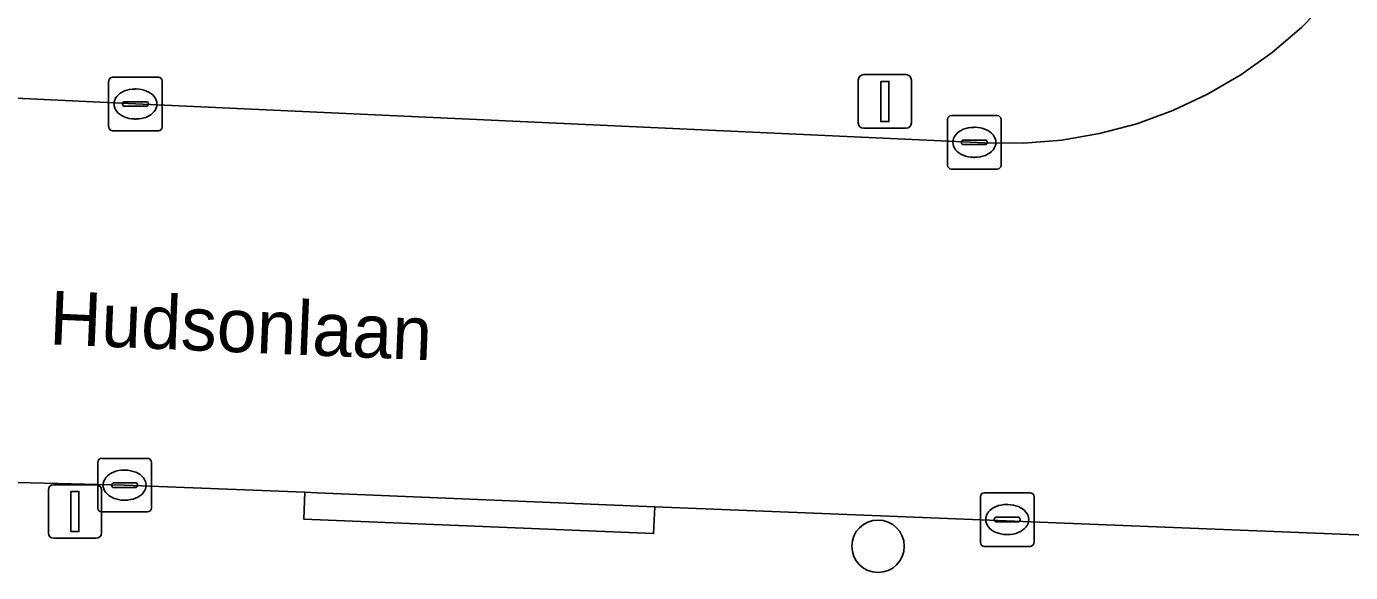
# Model space of a CAD drawing. Extents: x 161248 to 161848, y 384871 to 385383.
# Drawn here: x 161662.78 to 161687.48, y 384939.05 to 384949.24 of the extents above; entities that cross this region are included whole.
import ezdxf

# ---------------------------------------------------------------- set-up
doc = ezdxf.new("R2010")
doc.units = 0
for name, color, linetype in [('IMGEO_Boom', 7, 'Continuous'), ('IMGEO_Kolk', 7, 'Continuous'), ('IMGEO_Lichtmast', 7, 'Continuous'), ('IMGEO_Openbare_ruimte_label', 7, 'Continuous'), ('IMGEO_Rijbaan_lokaal_open', 7, 'Continuous'), ('IMGEO_Voetpad_open', 7, 'Continuous')]:
    doc.layers.add(name, color=color, linetype=linetype)

msp = doc.modelspace()

# ---------------------------------------------------------------- linework, layer by layer
at = {"layer": 'IMGEO_Boom'}
msp.add_circle((161678.665, 384939.544), 0.489, dxfattribs=at)
at = {"layer": 'IMGEO_Kolk'}
for p, q in [((161664.387, 384948.293), (161665.239, 384948.293)), ((161664.312, 384947.367), (161664.312, 384948.219)), ((161664.8, 384948.073), (161664.825, 384948.073)), ((161665.313, 384948.219), (161665.313, 384947.367)), ((161664.571, 384947.787), (161664.571, 384947.799)), ((161665.009, 384947.75), (161664.611, 384947.75)), ((161664.614, 384947.836), (161665.012, 384947.836)), ((161665.055, 384947.799), (161665.055, 384947.787)), ((161664.823, 384947.513), (161664.798, 384947.513)), ((161679.961, 384946.652), (161679.961, 384947.504)), ((161680.036, 384947.578), (161680.888, 384947.578)), ((161680.962, 384947.504), (161680.962, 384946.652)), ((161665.239, 384947.293), (161664.387, 384947.293)), ((161680.449, 384947.358), (161680.474, 384947.358)), ((161680.22, 384947.072), (161680.22, 384947.084)), ((161680.658, 384947.035), (161680.26, 384947.035)), ((161680.263, 384947.121), (161680.661, 384947.121)), ((161680.704, 384947.084), (161680.704, 384947.072)), ((161680.472, 384946.798), (161680.447, 384946.798)), ((161680.888, 384946.578), (161680.036, 384946.578)), ((161664.109, 384940.258), (161664.109, 384941.11)), ((161664.184, 384941.184), (161665.036, 384941.184)), ((161665.11, 384941.11), (161665.11, 384940.258)), ((161664.597, 384940.964), (161664.622, 384940.964)), ((161664.368, 384940.678), (161664.368, 384940.69)), ((161664.806, 384940.641), (161664.408, 384940.641)), ((161664.411, 384940.727), (161664.809, 384940.727)), ((161664.852, 384940.69), (161664.852, 384940.678)), ((161664.62, 384940.404), (161664.595, 384940.404)), ((161680.574, 384939.617), (161680.574, 384940.469)), ((161680.649, 384940.543), (161681.501, 384940.543)), ((161681.575, 384940.469), (161681.575, 384939.617)), ((161665.036, 384940.184), (161664.184, 384940.184)), ((161680.876, 384940.086), (161681.274, 384940.086)), ((161681.062, 384940.323), (161681.087, 384940.323)), ((161680.833, 384940.037), (161680.833, 384940.049)), ((161681.271, 384940), (161680.873, 384940)), ((161681.317, 384940.049), (161681.317, 384940.037)), ((161681.085, 384939.763), (161681.06, 384939.763)), ((161681.501, 384939.543), (161680.649, 384939.543))]:
    msp.add_line(p, q, dxfattribs=at)
for points in [[(161664.387, 384948.293), (161665.239, 384948.293)], [(161664.312, 384947.367), (161664.312, 384948.219)], [(161665.313, 384948.219), (161665.313, 384947.367)], [(161679.961, 384946.652), (161679.961, 384947.504)], [(161680.036, 384947.578), (161680.888, 384947.578)], [(161680.962, 384947.504), (161680.962, 384946.652)], [(161665.239, 384947.293), (161664.387, 384947.293)], [(161680.888, 384946.578), (161680.036, 384946.578)], [(161664.109, 384940.258), (161664.109, 384941.11)], [(161664.184, 384941.184), (161665.036, 384941.184)], [(161665.11, 384941.11), (161665.11, 384940.258)], [(161680.574, 384939.617), (161680.574, 384940.469)], [(161680.649, 384940.543), (161681.501, 384940.543)], [(161681.575, 384940.469), (161681.575, 384939.617)], [(161665.036, 384940.184), (161664.184, 384940.184)], [(161681.501, 384939.543), (161680.649, 384939.543)]]:
    msp.add_lwpolyline(points, dxfattribs=at)
for centre, radius, start, end in [((161664.389, 384948.217), 0.0765, 91.552, 178.448), ((161664.389, 384948.217), 0.0765, 91.552, 178.448), ((161665.237, 384948.217), 0.0765, 1.552, 88.448), ((161665.237, 384948.217), 0.0765, 1.552, 88.448), ((161664.611, 384947.796), 0.0403, 85.8775, 175.7526), ((161664.608, 384947.786), 0.0366, 178.938, 274.7102), ((161665.012, 384947.793), 0.043, 264.8664, 352.4533), ((161665.016, 384947.798), 0.0386, 1.7309, 96.639), ((161680.038, 384947.502), 0.0765, 91.552, 178.448), ((161680.038, 384947.502), 0.0765, 91.552, 178.448), ((161680.886, 384947.502), 0.0765, 1.552, 88.448), ((161680.886, 384947.502), 0.0765, 1.552, 88.448), ((161664.389, 384947.369), 0.0765, 181.552, 268.448), ((161664.389, 384947.369), 0.0765, 181.552, 268.448), ((161665.237, 384947.369), 0.0765, 271.552, 358.448), ((161665.237, 384947.369), 0.0765, 271.552, 358.448), ((161680.26, 384947.081), 0.0403, 85.8775, 175.7526), ((161680.257, 384947.071), 0.0366, 178.938, 274.7102), ((161680.661, 384947.078), 0.043, 264.8664, 352.4533), ((161680.665, 384947.083), 0.0386, 1.7309, 96.639), ((161680.038, 384946.654), 0.0765, 181.552, 268.448), ((161680.038, 384946.654), 0.0765, 181.552, 268.448), ((161680.886, 384946.654), 0.0765, 271.552, 358.448), ((161680.886, 384946.654), 0.0765, 271.552, 358.448), ((161664.186, 384941.108), 0.0765, 91.552, 178.448), ((161664.186, 384941.108), 0.0765, 91.552, 178.448), ((161665.034, 384941.108), 0.0765, 1.552, 88.448), ((161665.034, 384941.108), 0.0765, 1.552, 88.448), ((161664.408, 384940.687), 0.0403, 85.8775, 175.7526), ((161664.405, 384940.677), 0.0366, 178.938, 274.7102), ((161664.809, 384940.684), 0.043, 264.8664, 352.4533), ((161664.813, 384940.689), 0.0386, 1.7309, 96.639), ((161680.651, 384940.467), 0.0765, 91.552, 178.448), ((161680.651, 384940.467), 0.0765, 91.552, 178.448), ((161681.499, 384940.467), 0.0765, 1.552, 88.448), ((161681.499, 384940.467), 0.0765, 1.552, 88.448), ((161664.186, 384940.26), 0.0765, 181.552, 268.448), ((161664.186, 384940.26), 0.0765, 181.552, 268.448), ((161665.034, 384940.26), 0.0765, 271.552, 358.448), ((161665.034, 384940.26), 0.0765, 271.552, 358.448), ((161680.873, 384940.046), 0.0403, 85.8775, 175.7526), ((161681.278, 384940.048), 0.0386, 1.7309, 96.639), ((161680.87, 384940.036), 0.0366, 178.938, 274.7102), ((161681.274, 384940.043), 0.043, 264.8664, 352.4533), ((161680.651, 384939.619), 0.0765, 181.552, 268.448), ((161680.651, 384939.619), 0.0765, 181.552, 268.448), ((161681.499, 384939.619), 0.0765, 271.552, 358.448), ((161681.499, 384939.619), 0.0765, 271.552, 358.448)]:
    msp.add_arc(centre, radius, start, end, dxfattribs=at)
for centre, major_axis, ratio, start_param, end_param in [((161664.799, 384947.793), (-0.387, 0.002), 0.722429, 4.712389, 7.853982), ((161664.824, 384947.793), (-0.39, 0.002), 0.717154, 1.570796, 4.712389), ((161680.448, 384947.078), (-0.387, 0.002), 0.722429, 4.712389, 7.853982), ((161680.473, 384947.078), (-0.39, 0.002), 0.717154, 1.570796, 4.712389), ((161664.596, 384940.684), (-0.387, 0.002), 0.722429, 4.712389, 7.853982), ((161664.621, 384940.684), (-0.39, 0.002), 0.717154, 1.570796, 4.712389), ((161681.061, 384940.043), (-0.387, 0.002), 0.722429, 4.712389, 7.853982), ((161681.086, 384940.043), (-0.39, 0.002), 0.717154, 1.570796, 4.712389)]:
    msp.add_ellipse(centre, major_axis=major_axis, ratio=ratio, start_param=start_param, end_param=end_param, dxfattribs=at)
at = {"layer": 'IMGEO_Lichtmast'}
for p, q in [((161678.297, 384947.44), (161678.297, 384948.24)), ((161678.297, 384948.24), (161678.297, 384947.44)), ((161678.397, 384948.34), (161679.187, 384948.34)), ((161679.187, 384948.34), (161678.397, 384948.34)), ((161679.287, 384948.24), (161679.287, 384947.44)), ((161679.287, 384947.44), (161679.287, 384948.24)), ((161679.187, 384947.34), (161678.397, 384947.34)), ((161678.397, 384947.34), (161679.187, 384947.34)), ((161663.188, 384939.793), (161663.188, 384940.593)), ((161663.188, 384940.593), (161663.188, 384939.793)), ((161663.288, 384940.693), (161664.078, 384940.693)), ((161664.078, 384940.693), (161663.288, 384940.693)), ((161664.178, 384940.593), (161664.178, 384939.793)), ((161664.178, 384939.793), (161664.178, 384940.593)), ((161664.078, 384939.693), (161663.288, 384939.693)), ((161663.288, 384939.693), (161664.078, 384939.693))]:
    msp.add_line(p, q, dxfattribs=at)
for points in [[(161678.717, 384948.215), (161678.867, 384948.215), (161678.867, 384947.465), (161678.717, 384947.465), (161678.717, 384948.215)], [(161663.608, 384940.568), (161663.758, 384940.568), (161663.758, 384939.818), (161663.608, 384939.818), (161663.608, 384940.568)]]:
    msp.add_lwpolyline(points, dxfattribs=at)
for centre, start, end in [((161678.397, 384948.24), 90, 180), ((161678.397, 384948.24), 90, 180), ((161679.187, 384948.24), 0, 90), ((161679.187, 384948.24), 360, 90), ((161678.397, 384947.44), 180, 270), ((161678.397, 384947.44), 180, 270), ((161679.187, 384947.44), 270, 0), ((161679.187, 384947.44), 270, 0), ((161663.288, 384940.593), 90, 180), ((161663.288, 384940.593), 90, 180), ((161664.078, 384940.593), 0, 90), ((161664.078, 384940.593), 360, 90), ((161663.288, 384939.793), 180, 270), ((161663.288, 384939.793), 180, 270), ((161664.078, 384939.793), 270, 0), ((161664.078, 384939.793), 270, 0)]:
    msp.add_arc(centre, 0.1, start, end, dxfattribs=at)
at = {"layer": 'IMGEO_Rijbaan_lokaal_open'}
msp.add_lwpolyline([(161687.065, 384949.731), (161686.563, 384949.219), (161686.018, 384948.753), (161685.433, 384948.338), (161684.814, 384947.976), (161684.165, 384947.672), (161683.491, 384947.426), (161682.798, 384947.242), (161682.091, 384947.121), (161681.376, 384947.063), (161680.659, 384947.069), (161664.813, 384947.793), (161661.913, 384947.934), (161661.612, 384940.759), (161664.61, 384940.684), (161667.973, 384940.551), (161668.201, 384940.542), (161674.499, 384940.279), (161695.406, 384939.447), (161697.013, 384979.259)], dxfattribs=at)
at = {"layer": 'IMGEO_Voetpad_open'}
for points in [[(161702.236, 384985.804), (161700.252, 384939.228), (161695.406, 384939.447), (161674.499, 384940.279), (161674.477, 384939.78), (161667.951, 384940.052), (161667.973, 384940.551), (161664.61, 384940.684), (161661.612, 384940.759)], [(161659.768, 384950.519), (161659.665, 384948.098), (161659.723, 384948.084), (161660.275, 384948.003), (161660.291, 384948.001), (161661.913, 384947.934), (161664.813, 384947.793), (161680.659, 384947.069), (161681.376, 384947.063), (161682.091, 384947.121), (161682.798, 384947.242), (161683.491, 384947.426), (161684.165, 384947.672), (161684.814, 384947.976), (161685.433, 384948.338), (161686.018, 384948.753), (161686.563, 384949.219), (161687.065, 384949.731)]]:
    msp.add_lwpolyline(points, dxfattribs=at)
msp.add_lwpolyline([(161667.973, 384940.551), (161667.951, 384940.052), (161674.477, 384939.78), (161674.499, 384940.279), (161668.201, 384940.542)], close=True, dxfattribs=at)

# ---------------------------------------------------------------- texts
at = {"layer": 'IMGEO_Openbare_ruimte_label'}
msp.add_text('Hudsonlaan', height=1, rotation=357.5926, dxfattribs=at).set_placement((161663.195, 384943.312))

doc.saveas('drawing.dxf')
